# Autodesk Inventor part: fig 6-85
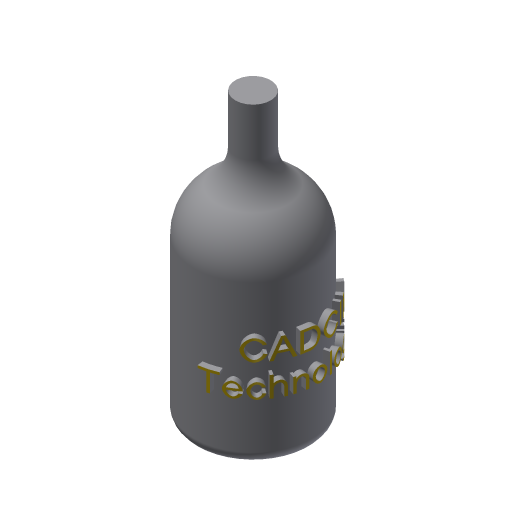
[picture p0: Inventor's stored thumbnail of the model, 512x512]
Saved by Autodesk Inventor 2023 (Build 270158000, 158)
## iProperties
Part Number: fig 6-85
Document SubType Name: Modeling
Created: 2002-12
Designer: deepak
Density: 1 g/cm^3
Material: Generic
Appearance: Default
Control State: 0
Master: False
Checked Out: False
Shininess: 64.0
Length Units: 11269
Angle Units: 11279
Time Units: 11290
Mass Units: 11283
Length Display Precision: 3
Angle Display Precision: 2
Compacted: True
Density: 0.0
Volumn: 0.0
Area: 0.0
PropertySet Name: Model Information
Author: deepak
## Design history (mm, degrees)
node "Sketch1"
sketch "Sketch2"
  geometry: L1 (-7.653, 24.992)-(-7.653, 16.776); L2 (-14.653, 3.659)-(-14.653, -3.57); L3 (-14.653, -3.57)-(-14.653, -23.329); L4 (-14.653, -23.329)-(-4.653, -23.329); L5 (-4.653, -23.329)-(-4.653, 24.992); L6 (-4.653, 24.992)-(-7.653, 24.992); A1 r 6.757 centre (-14.41, 16.776) between (-10.649, 11.163) and (-7.653, 16.776); A2 r 9.033 centre (-5.62, 3.659) between (-10.649, 11.163) and (-14.653, 3.659)
  constraints: 12 end point, 4 point on circle, 3 tangent, 2 centre point, 2 parallel, 2 perpendicular, 1 collinear, 1 vertical
  dimensions: "d0" = 3 distance of L5.end L1.start; "d1" = 10 distance of L3.end L4.end
revolve "Revolution1" sketch "Sketch2" stored, may be unused: angle "d2" = 90 deg
fillet "Fillet1" dims "d3" = 2
workplane "Work Plane1"
workplane "Work Plane2"
sketch "Sketch3"
  geometry: L1 (-24.815, -3.793)-(24.913, -3.793); L2 (24.913, -3.793)-(24.913, -8.382); L3 (24.913, -8.382)-(-24.815, -8.382); L4 (-24.815, -8.382)-(-24.815, -3.793)
  constraints: 2 other
emboss "Emboss1" sketch "Sketch3" dims "d5" = 1, "d6" = 0
body "Solid1"
other parameters: "d4" = 3.5
